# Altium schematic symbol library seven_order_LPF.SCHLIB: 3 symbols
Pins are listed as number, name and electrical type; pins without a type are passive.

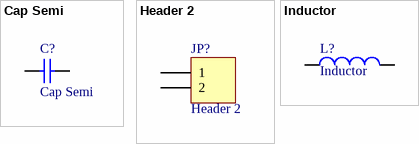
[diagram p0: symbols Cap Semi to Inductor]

## Cap Semi
designator C?
Capacitor (Semiconductor SIM Model); Manufacturer: Generic Components; Class I: Passive; Value: 100pF
footprint C3216-1206
simulation model CAP (Semiconductor Capacitor)
signal-integrity model Cap Semi
pins: 1, 2

## Header 2
designator JP?
Header, 2-Pin; Manufacturer: Generic Components; Class I: Connector
footprint HDR1X2
signal-integrity model Connector
pins: 1, 2

## Inductor
designator L?
Manufacturer: Generic Components; Class I: Passive; Value: 10mH
footprint C1005-0402
simulation model INDUCTOR (Inductor)
signal-integrity model Inductor
pins: 1, 2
